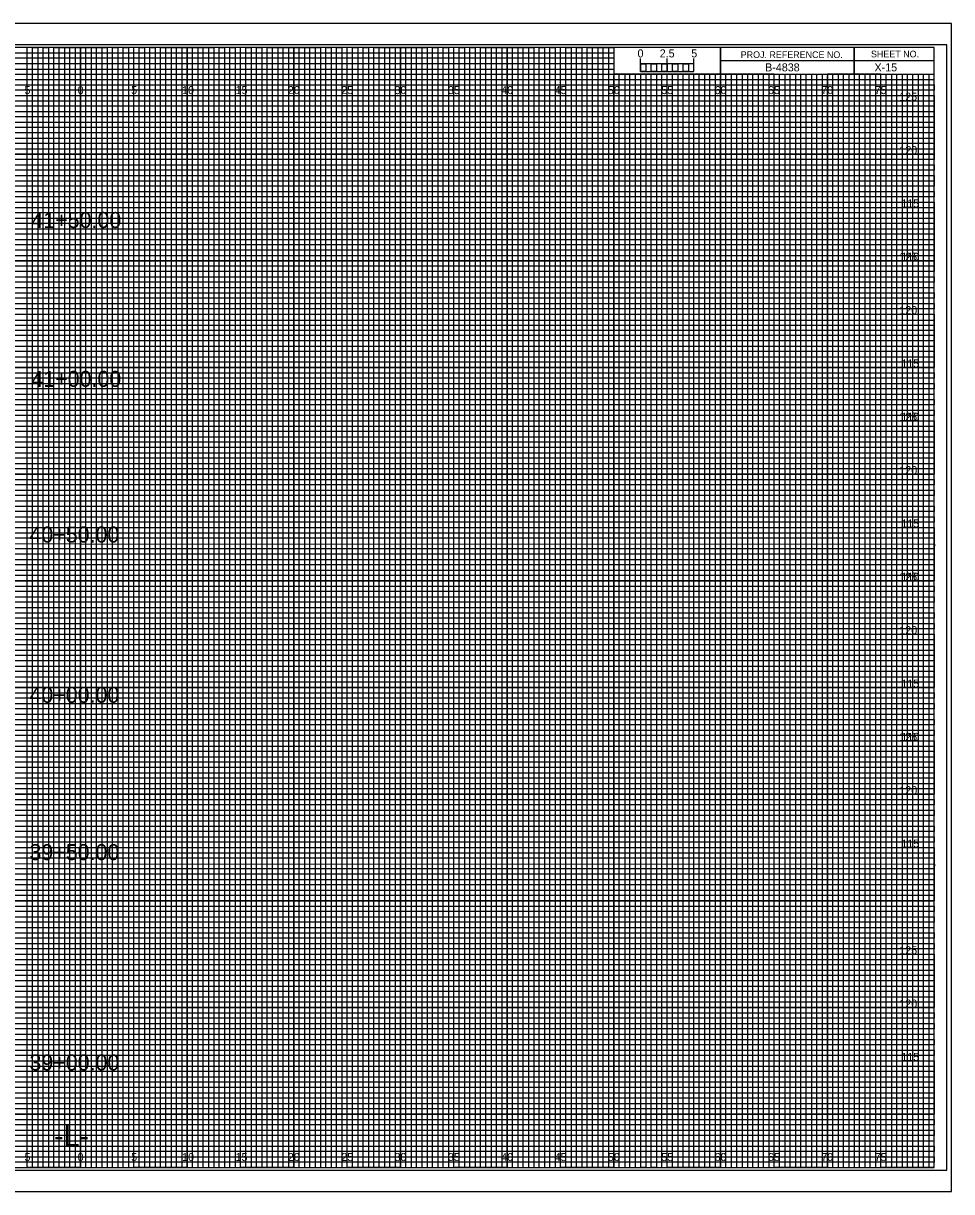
# Model space of a CAD drawing. Extents: x -7 to 182, y -2 to 1647.
# Drawn here: x 74.6 to 161.7, y 1427.8 to 1537.2 of the extents above; entities that cross this region are included whole.
import ezdxf

# ---------------------------------------------------------------- set-up
doc = ezdxf.new("R2010")
doc.units = 0
for name, color, linetype in [('Exist CMT Pavement', 7, 'Continuous'), ('Exist Cross Section Cell', 7, 'Continuous'), ('Exist XS Ground Line', 7, 'Continuous'), ('Prop CMT Pvmt Course 1', 7, 'Continuous'), ('Prop CMT Pvmt Course 2', 7, 'Continuous'), ('Prop CMT Pvmt Course 2 Wedge', 7, 'Continuous'), ('Prop CMT Pvmt Course 3', 7, 'Continuous'), ('Prop CMT Pvmt Surface', 7, 'Continuous'), ('Prop CMT Pvmt Surface Shoulder', 7, 'Continuous'), ('Prop CMT Pvmt Wedge Surface 1', 7, 'Continuous'), ('Prop CMT Pvmt Wedge Surface 2', 7, 'Continuous'), ('Prop CMT Pvmt Wedge Surface 3', 7, 'Continuous'), ('Prop CMT Shld Paved Course 1', 7, 'Continuous'), ('Prop CMT Shld Paved Course 2', 7, 'Continuous'), ('Prop CMT Shld Paved Course 3', 7, 'Continuous'), ('Prop CMT Slope Grass', 7, 'Continuous'), ('Prop CMT Subgrade Earthwork', 7, 'Continuous')]:
    doc.layers.add(name, color=color, linetype=linetype)

msp = doc.modelspace()

# ---------------------------------------------------------------- linework, layer by layer
at = {"layer": 'Exist XS Ground Line'}
for p, q in [((75, 1535), (70, 1535)), ((75, 1430), (75, 1535)), ((85, 1535), (80, 1535)), ((80, 1535), (80, 1430)), ((85, 1430), (85, 1535)), ((95, 1535), (90, 1535)), ((90, 1535), (90, 1430)), ((95, 1430), (95, 1535)), ((105, 1535), (100, 1535)), ((100, 1535), (100, 1430)), ((105, 1430), (105, 1535)), ((115, 1535), (110, 1535)), ((110, 1535), (110, 1430)), ((115, 1430), (115, 1535)), ((125, 1535), (120, 1535)), ((120, 1535), (120, 1430)), ((125, 1430), (125, 1535)), ((130, 1535), (130, 1430)), ((135, 1430), (135, 1532.5)), ((145, 1532.5), (140, 1532.5)), ((140, 1532.5), (140, 1430)), ((145, 1430), (145, 1532.5)), ((155, 1532.5), (150, 1532.5)), ((150, 1532.5), (150, 1430)), ((155, 1430), (155, 1532.5)), ((80, 1430), (75, 1430)), ((90, 1430), (85, 1430)), ((100, 1430), (95, 1430)), ((110, 1430), (105, 1430)), ((120, 1430), (115, 1430)), ((130, 1430), (125, 1430)), ((140, 1430), (135, 1430)), ((150, 1430), (145, 1430)), ((160, 1430), (155, 1430)), ((160, 1430), (160, 1430))]:
    msp.add_line(p, q, dxfattribs=at)
for points in [[(0, 1530), (160, 1530), (160, 1525), (0, 1525)], [(0, 1520), (160, 1520), (160, 1515), (0, 1515)], [(0, 1510), (160, 1510), (160, 1505), (0, 1505)], [(0, 1500), (160, 1500), (160, 1495), (0, 1495)], [(0, 1490), (160, 1490), (160, 1485), (0, 1485)], [(0, 1480), (160, 1480), (160, 1475), (0, 1475)], [(0, 1470), (160, 1470), (160, 1465), (0, 1465)], [(0, 1460), (160, 1460), (160, 1455), (0, 1455)], [(0, 1450), (160, 1450), (160, 1445), (0, 1445)], [(0, 1440), (160, 1440), (160, 1435), (0, 1435)]]:
    msp.add_lwpolyline(points, dxfattribs=at)
at = {"layer": 'Prop CMT Pvmt Course 2'}
for p, q in [((132.5, 1532.75), (132.5, 1533.95)), ((132.5, 1533.45), (132.5, 1533.95)), ((135, 1532.75), (135, 1533.95)), ((137.5, 1532.75), (137.5, 1533.95)), ((137.5, 1533.45), (137.5, 1533.95))]:
    msp.add_line(p, q, dxfattribs=at)
for points in [[(137.5, 1533.45), (132.5, 1533.45), (132.5, 1532.75), (137.5, 1532.75)], [(132.5, 1533.45), (133, 1533.45), (133, 1532.75), (132.5, 1532.75)], [(133.5, 1533.45), (134, 1533.45), (134, 1532.75), (133.5, 1532.75)], [(134.5, 1533.45), (135, 1533.45), (135, 1532.75), (134.5, 1532.75)], [(135.5, 1533.45), (136, 1533.45), (136, 1532.75), (135.5, 1532.75)], [(136.5, 1533.45), (137, 1533.45), (137, 1532.75), (136.5, 1532.75)]]:
    msp.add_lwpolyline(points, close=True, dxfattribs=at)
at = {"layer": 'Prop CMT Pvmt Course 3'}
msp.add_lwpolyline([(-6.7, 1427.75), (161.65, 1427.75), (161.65, 1537.25), (-6.7, 1537.25)], close=True, dxfattribs=at)
at = {"layer": 'Prop CMT Pvmt Wedge Surface 1'}
for p, q in [((0, 1534.5), (130, 1534.5)), ((130, 1534.5), (130, 1533.99)), ((130, 1533.99), (0, 1533.99)), ((0, 1533.5), (130, 1533.5)), ((130, 1533.5), (130, 1532.94)), ((130, 1532.94), (0, 1532.94)), ((0, 1532), (160, 1532))]:
    msp.add_line(p, q, dxfattribs=at)
for points in [[(0, 1531.5), (135, 1531.5), (160, 1531.5), (160, 1531), (0, 1531)], [(0, 1530.5), (160, 1530.5), (160, 1529.5), (0, 1529.5)], [(0, 1529), (160, 1529), (160, 1528.5), (0, 1528.49)], [(0, 1528), (160, 1528), (160, 1527), (0, 1527)], [(0, 1526.5), (160, 1526.5), (160, 1526), (0, 1526)], [(0, 1525.5), (160, 1525.5), (160, 1524.5), (0, 1524.5)], [(0, 1524), (160, 1524), (160, 1523.5), (0, 1523.5)], [(0, 1523), (160, 1523), (160, 1522), (0, 1522)], [(0, 1521.5), (160, 1521.5), (160, 1521), (0, 1521)], [(0, 1520.5), (160, 1520.5), (160, 1519.5), (0, 1519.5)], [(0, 1519), (160, 1519), (160, 1518.5), (0, 1518.5)], [(0, 1518), (160, 1518), (160, 1516.98), (160, 1516.5), (160, 1516), (0, 1516)], [(0, 1517), (160, 1517), (160, 1516.5), (0, 1516.5)], [(0, 1515.5), (160, 1515.5), (160, 1514.5), (0, 1514.52)], [(0, 1514.52), (160, 1514.5), (160, 1514), (0, 1514)], [(0, 1513.5), (160, 1513.5), (160, 1513), (0, 1513)], [(0, 1512), (160, 1512), (160, 1511.5), (0, 1511.5)], [(0, 1511), (160, 1511), (160, 1510.5), (0, 1510.5)], [(-0.04, 1509.44), (160, 1509.44), (160, 1508.94), (-0.04, 1508.94)], [(0, 1508.5), (160, 1508.5), (160, 1508), (0, 1508)], [(0, 1507), (160, 1507), (160, 1506.5), (0, 1506.5)], [(0, 1506), (160, 1506), (160, 1505.5), (0, 1505.5)], [(0, 1504.5), (160, 1504.5), (160, 1504), (0, 1504)], [(0, 1503.5), (160, 1503.5), (160, 1503), (0, 1503)], [(0, 1502), (160, 1502), (160, 1501.5), (0, 1501.5)], [(0, 1501), (160, 1501), (160, 1500.5), (0, 1500.5)], [(0, 1499.5), (160, 1499.5), (160, 1498.99), (0, 1499)], [(0, 1498.5), (160, 1498.5), (160, 1498), (0, 1498)], [(0, 1497), (160, 1497), (160, 1496.5), (0, 1496.5)], [(0, 1496), (160, 1496), (160, 1495.5), (0, 1495.5)], [(0, 1494.5), (160, 1494.5), (160, 1494), (0, 1494)], [(0, 1493.5), (160, 1493.5), (160, 1493), (0, 1493)], [(0, 1492), (160, 1492), (160, 1491.5), (0, 1491.5)], [(0, 1491), (160, 1491), (160, 1490.5), (0, 1490.5)], [(0, 1489.5), (160, 1489.5), (160, 1489), (0, 1489)], [(0, 1488.5), (160.03, 1488.45), (160, 1488), (0, 1488)], [(0, 1487), (160, 1487), (160, 1486.5), (0, 1486.5)], [(0, 1486), (160, 1486), (160, 1485.5), (0, 1485.5)], [(0, 1484.5), (160, 1484.5), (160, 1484), (0, 1484)], [(0, 1483.5), (160, 1483.5), (160, 1483), (0, 1483)], [(0, 1482), (160, 1482), (160, 1481.5), (0, 1481.5)], [(0, 1481), (160, 1481), (160, 1480.5), (0, 1480.5)], [(0, 1479.5), (160, 1479.5), (160, 1479), (0, 1479)], [(0, 1478.5), (160, 1478.5), (160, 1478), (0, 1478)], [(0, 1477), (160, 1477), (160, 1476.5), (0, 1476.5)], [(0, 1476), (160, 1476), (160, 1475.5), (0, 1475.5)], [(0, 1474.5), (160, 1474.5), (160, 1474), (0, 1474)], [(0, 1473.5), (160, 1473.5), (160, 1473), (0, 1473)], [(0, 1472), (160, 1472), (160, 1471.5), (0, 1471.5)], [(0, 1471), (160, 1471), (160, 1470.5), (0, 1470.5)], [(0, 1469.5), (160, 1469.5), (160, 1468.99), (0, 1469)], [(0, 1468.5), (160, 1468.5), (160, 1468), (0, 1468)], [(0, 1467), (160, 1467), (160, 1466.5), (0, 1466.5)], [(0, 1466), (160, 1466), (160, 1465.5), (0, 1465.5)], [(0, 1464.5), (160, 1464.5), (160, 1464), (0, 1464)], [(0, 1463.5), (160, 1463.5), (160, 1463), (0, 1463)], [(0, 1462), (160, 1462), (160, 1461.5), (0, 1461.5)], [(0, 1461), (160, 1461), (160, 1460.5), (0, 1460.5)], [(0, 1459.5), (160, 1459.5), (160, 1459), (0, 1459)], [(0, 1458.5), (160.03, 1458.45), (160, 1458), (0, 1458)], [(0, 1457), (160, 1457), (160, 1456.5), (0, 1456.5)], [(0, 1456), (160, 1456), (160, 1455.5), (0, 1455.5)], [(0, 1454.5), (160, 1454.5), (160, 1454), (0, 1454)], [(0, 1453.5), (160, 1453.5), (160, 1453), (0, 1453)], [(0, 1452), (160, 1452), (160, 1451.5), (0, 1451.5)], [(0, 1451), (160, 1451), (160, 1450.5), (0, 1450.5)], [(0, 1449.5), (160, 1449.5), (160, 1449), (0, 1449)], [(0, 1448.5), (160, 1448.5), (160, 1448), (0, 1448)], [(0, 1447), (160, 1447), (160, 1446.5), (0, 1446.5)], [(0, 1446), (160, 1446), (160, 1445.5), (0, 1445.5)], [(0, 1444.5), (160, 1444.5), (160, 1444), (0, 1444)], [(0, 1443.5), (160, 1443.5), (160, 1443), (0, 1443)], [(0, 1442), (160, 1442), (160, 1441.5), (0, 1441.5)], [(0, 1441), (160, 1441), (160, 1440.5), (0, 1440.5)], [(0, 1439.5), (160, 1439.5), (160, 1439), (0, 1439)], [(0, 1438.5), (160, 1438.5), (160, 1438), (0, 1438)], [(0, 1437), (160, 1437), (160, 1436.5), (0, 1436.5)], [(0, 1436), (160, 1436), (160, 1435.5), (0, 1435.5)], [(0, 1434.5), (160, 1434.5), (160, 1434), (0, 1434)], [(0, 1433.5), (160, 1433.5), (160, 1433), (0, 1433)], [(0, 1432), (160, 1432), (160, 1431.5), (0, 1431.5)], [(0, 1431), (160, 1431), (160, 1430.5), (0, 1430.5)]]:
    msp.add_lwpolyline(points, dxfattribs=at)
at = {"layer": 'Prop CMT Pvmt Wedge Surface 2'}
for p, q in [((152.5, 1535), (152.5, 1532.5)), ((152.5, 1532.5), (152.5, 1535)), ((160, 1533.75), (140, 1533.75)), ((140, 1533.75), (140, 1532.5)), ((140, 1532.5), (160, 1532.5))]:
    msp.add_line(p, q, dxfattribs=at)
for points in [[(160, 1535), (0, 1535), (0, 1430), (160, 1430)], [(140, 1535), (130, 1535), (130, 1532.52), (140, 1532.52)], [(160, 1535), (140, 1535), (140, 1532.5), (160, 1532.5)]]:
    msp.add_lwpolyline(points, close=True, dxfattribs=at)
at = {"layer": 'Prop CMT Pvmt Wedge Surface 3'}
for p, q in [((133.5, 1532.5), (133, 1532.5)), ((133, 1532.5), (133, 1430)), ((133.5, 1430), (133.5, 1532.5)), ((134.5, 1532.5), (134, 1532.5)), ((134, 1532.5), (134, 1430)), ((134.5, 1430), (134.5, 1532.5)), ((133, 1430), (132.5, 1430)), ((134, 1430), (133.5, 1430))]:
    msp.add_line(p, q, dxfattribs=at)
for points in [[(75, 1430), (75.5, 1430), (75.5, 1535), (76, 1535), (76, 1430)], [(76, 1430), (76.5, 1430), (76.5, 1535), (77, 1535), (77, 1430)], [(77.5, 1430), (78, 1430), (78, 1535), (78.5, 1535), (78.5, 1430)], [(78.5, 1430), (79, 1430), (79, 1535), (79.5, 1535), (79.5, 1430)], [(80, 1430), (80.5, 1430), (80.5, 1535), (81, 1535), (81, 1430)], [(81, 1430), (81.5, 1430), (81.5, 1535), (82, 1535), (82, 1430)], [(82.5, 1430), (83, 1430), (83, 1535), (83.5, 1535), (83.5, 1430)], [(83.5, 1430), (84, 1430), (84, 1535), (84.5, 1535), (84.5, 1430)], [(85, 1430), (85.5, 1430), (85.5, 1535), (86, 1535), (86, 1430)], [(86, 1430), (86.5, 1430), (86.5, 1535), (87, 1535), (87, 1430)], [(87.5, 1430), (88, 1430), (88, 1535), (88.5, 1535), (88.5, 1430)], [(88.5, 1430), (89, 1430), (89, 1535), (89.5, 1535), (89.5, 1430)], [(90, 1430), (90.5, 1430), (90.5, 1535), (91, 1535), (91, 1430)], [(91, 1430), (91.5, 1430), (91.5, 1535), (92, 1535), (92, 1430)], [(92.5, 1430), (93, 1430), (93, 1535), (93.5, 1535), (93.5, 1430)], [(93.5, 1430), (94, 1430), (94, 1535), (94.5, 1535), (94.5, 1430)], [(95, 1430), (95.5, 1430), (95.5, 1535), (96, 1535), (96, 1430)], [(96, 1430), (96.5, 1430), (96.5, 1535), (97, 1535), (97, 1430)], [(97.5, 1430), (98, 1430), (98, 1535), (98.5, 1535), (98.5, 1430)], [(98.5, 1430), (99, 1430), (99, 1535), (99.5, 1535), (99.5, 1430)], [(100, 1430), (100.5, 1430), (100.5, 1535), (101, 1535), (101, 1430)], [(101, 1430), (101.5, 1430), (101.5, 1535), (102, 1535), (102, 1430)], [(102.5, 1430), (103, 1430), (103, 1535), (103.5, 1535), (103.5, 1430)], [(103.5, 1430), (104, 1430), (104, 1535), (104.5, 1535), (104.5, 1430)], [(105, 1430), (105.5, 1430), (105.5, 1535), (106, 1535), (106, 1430)], [(106, 1430), (106.5, 1430), (106.5, 1535), (107, 1535), (107, 1430)], [(107.5, 1430), (108, 1430), (108, 1535), (108.5, 1535), (108.5, 1430)], [(108.5, 1430), (109, 1430), (109, 1535), (109.5, 1535), (109.5, 1430)], [(110, 1430), (110.5, 1430), (110.5, 1535), (111, 1535), (111, 1430)], [(111, 1430), (111.5, 1430), (111.5, 1535), (112, 1535), (112, 1430)], [(112.5, 1430), (113, 1430), (113, 1535), (113.5, 1535), (113.5, 1430)], [(113.5, 1430), (114, 1430), (114, 1535), (114.5, 1535), (114.5, 1430)], [(115, 1430), (115.5, 1430), (115.5, 1535), (116, 1535), (116, 1430)], [(116, 1430), (116.5, 1430), (116.5, 1535), (117, 1535), (117, 1430)], [(117.5, 1430), (118, 1430), (118, 1535), (118.5, 1535), (118.5, 1430)], [(118.5, 1430), (119, 1430), (119, 1535), (119.5, 1535), (119.5, 1430)], [(120, 1430), (120.5, 1430), (120.5, 1535), (121, 1535), (121, 1430)], [(121, 1430), (121.5, 1430), (121.5, 1535), (122, 1535), (122, 1430)], [(122.5, 1430), (123, 1430), (123, 1535), (123.5, 1535), (123.5, 1430)], [(123.5, 1430), (124, 1430), (124, 1535), (124.5, 1535), (124.5, 1430)], [(125, 1430), (125.5, 1430), (125.5, 1535), (126, 1535), (126, 1430)], [(126, 1430), (126.5, 1430), (126.5, 1535), (127, 1535), (127, 1430)], [(127.5, 1430), (128, 1430), (128, 1535), (128.5, 1535), (128.5, 1430)], [(128.5, 1430), (129, 1430), (129, 1535), (129.5, 1535), (129.5, 1430)], [(130, 1430), (130.5, 1430), (130.5, 1532.5), (131.01, 1532.5), (131.01, 1430)], [(131, 1430), (131.5, 1430), (131.5, 1532.5), (132, 1532.5), (132, 1430)], [(135, 1430), (135.49, 1430), (135.49, 1532.5), (136, 1532.5), (136, 1430)], [(136, 1430), (136.5, 1430), (136.5, 1532.5), (137.03, 1532.5), (137.03, 1430)], [(137.5, 1430), (138, 1430), (138, 1532.5), (138.5, 1532.5), (138.5, 1430)], [(138.5, 1430), (139, 1430), (139, 1532.5), (139.5, 1532.5), (139.5, 1430)], [(140, 1430), (140.5, 1430), (140.5, 1532.5), (141, 1532.5), (141, 1430)], [(141, 1430), (141.5, 1430), (141.5, 1532.5), (142, 1532.5), (142, 1430)], [(142.5, 1430), (143, 1430), (143, 1532.5), (143.5, 1532.5), (143.5, 1430)], [(143.5, 1430), (144, 1430), (144, 1532.5), (144.5, 1532.5), (144.5, 1430)], [(145, 1430), (145.5, 1430), (145.5, 1532.5), (146, 1532.5), (146, 1430)], [(146, 1430), (146.5, 1430), (146.5, 1532.5), (147, 1532.5), (147, 1430)], [(147.5, 1430), (148, 1430), (148, 1532.5), (148.5, 1532.5), (148.5, 1430)], [(148.5, 1430), (149, 1430), (149, 1532.5), (149.5, 1532.5), (149.5, 1430)], [(150, 1430), (150.5, 1430), (150.5, 1532.5), (151, 1532.5), (151, 1430)], [(151, 1430), (151.5, 1430), (151.5, 1532.5), (152, 1532.5), (152, 1430)], [(152.5, 1430), (153, 1430), (153, 1532.5), (153.5, 1532.5), (153.5, 1430)], [(153.5, 1430), (154, 1430), (154, 1532.5), (154.5, 1532.5), (154.5, 1430)], [(155, 1430), (155.5, 1430), (155.5, 1532.5), (156, 1532.5), (156, 1430)], [(156, 1430), (156.5, 1430), (156.5, 1532.5), (157, 1532.5), (157, 1430)], [(157.5, 1430), (158, 1430), (158, 1532.5), (158.5, 1532.5), (158.5, 1430)], [(158.5, 1430), (159, 1430), (159, 1532.5), (159.5, 1532.5), (159.5, 1430)]]:
    msp.add_lwpolyline(points, dxfattribs=at)
at = {"layer": 'Prop CMT Shld Paved Course 1'}
for p, q in [((75, 1430), (75, 1535)), ((80, 1430), (80, 1535)), ((85, 1430), (85, 1535)), ((90, 1430), (90, 1535)), ((95, 1430), (95, 1535)), ((100, 1430), (100, 1535)), ((105, 1430), (105, 1535)), ((110, 1430), (110, 1535)), ((115, 1430), (115, 1535)), ((120, 1430), (120, 1535)), ((125, 1430), (125, 1535)), ((130, 1430), (130, 1532.34)), ((135, 1430), (135, 1532.34)), ((140, 1430), (140, 1532.34)), ((145, 1430), (145, 1532.34)), ((150, 1430), (150, 1532.34)), ((155, 1430), (155, 1532.34)), ((0, 1530), (160, 1530)), ((0, 1525), (160, 1525)), ((0, 1520), (160, 1520)), ((0, 1515), (160, 1515)), ((0, 1510), (160, 1510)), ((0, 1505), (160, 1505)), ((0, 1500), (160, 1500)), ((0, 1495), (160, 1495)), ((0, 1490), (160, 1490)), ((0, 1485), (160, 1485)), ((0, 1480), (160, 1480)), ((0, 1475), (160, 1475)), ((0, 1470), (160, 1470)), ((0, 1465), (160, 1465)), ((0, 1460), (160, 1460)), ((0, 1455), (160, 1455)), ((0, 1450), (160, 1450)), ((0, 1445), (160, 1445)), ((0, 1440), (160, 1440)), ((0, 1435), (160, 1435))]:
    msp.add_line(p, q, dxfattribs=at)
at = {"layer": 'Prop CMT Shld Paved Course 2'}
for p, q in [((161.65, 1537.25), (-6.7, 1537.25)), ((-6.7, 1427.75), (161.65, 1427.75))]:
    msp.add_line(p, q, dxfattribs=at)
at = {"layer": 'Prop CMT Slope Grass'}
msp.add_lwpolyline([(-5.4, 1429.75), (161.2, 1429.75), (161.2, 1535.25), (-5.4, 1535.25)], close=True, dxfattribs=at)
at = {"layer": 'Prop CMT Subgrade Earthwork'}
for points in [[(72.5, 1430), (77.5, 1430), (77.5, 1535), (82.5, 1535), (82.5, 1430), (87.5, 1430), (87.5, 1535), (92.5, 1535), (92.5, 1430), (97.5, 1430), (97.5, 1535), (102.5, 1535), (102.5, 1430), (107.5, 1430), (107.5, 1535), (112.5, 1535), (112.5, 1430), (117.5, 1430), (117.5, 1535), (122.5, 1535), (122.5, 1430), (127.5, 1430), (127.5, 1535), (129.97, 1535), (130, 1535), (130, 1532.5), (132.5, 1532.5), (132.5, 1430), (137.5, 1430), (137.5, 1532.5), (142.5, 1532.5), (142.5, 1430), (147.5, 1430), (147.5, 1532.5), (152.5, 1532.5), (152.5, 1430), (157.5, 1430), (157.5, 1532.5)], [(0, 1532.5), (137.5, 1532.5)], [(0, 1522.5), (160, 1522.5), (160, 1527.5), (0, 1527.5)], [(0, 1512.5), (160, 1512.5), (160, 1517.5), (0, 1517.5)], [(0, 1502.5), (160, 1502.5), (160, 1507.5), (0, 1507.5)], [(0, 1492.5), (160, 1492.5), (160, 1497.5), (0, 1497.5)], [(0, 1482.5), (160, 1482.5), (160, 1487.5), (0, 1487.5)], [(0, 1472.5), (160, 1472.5), (160, 1477.5), (0, 1477.5)], [(0, 1462.5), (160, 1462.5), (160, 1467.5), (0, 1467.5)], [(0, 1452.5), (160, 1452.5), (160, 1457.5), (0, 1457.5)], [(0, 1442.5), (160, 1442.5), (160, 1447.5), (0, 1447.5)], [(0, 1432.5), (160, 1432.5), (160, 1437.5), (0, 1437.5)]]:
    msp.add_lwpolyline(points, dxfattribs=at)

# ---------------------------------------------------------------- texts
at = {"layer": 'Exist CMT Pavement'}
for s, p in [('41+50.00', (75.39, 1518.07)), ('41+00.00', (75.39, 1503.18)), ('40+50.00', (75.21, 1488.59)), ('40+00.00', (75.21, 1473.57)), ('39+50.00', (75.21, 1458.82)), ('39+00.00', (75.21, 1439.11))]:
    msp.add_text(s, height=1.5, dxfattribs=at).set_placement(p)
at = {"layer": 'Exist Cross Section Cell'}
for s, p in [('5', (74.74, 1530.62)), ('0', (79.73, 1530.62)), ('0', (79.73, 1530.62)), ('5', (84.74, 1530.62)), ('10', (89.52, 1530.62)), ('15', (94.53, 1530.62)), ('20', (99.43, 1530.62)), ('25', (104.44, 1530.62)), ('30', (109.43, 1530.62)), ('35', (114.44, 1530.62)), ('40', (119.43, 1530.62)), ('45', (124.44, 1530.62)), ('50', (129.43, 1530.62)), ('55', (134.44, 1530.62)), ('60', (139.43, 1530.62)), ('65', (144.44, 1530.62)), ('70', (149.43, 1530.62)), ('75', (154.44, 1530.62)), ('5', (74.74, 1430.62)), ('0', (79.73, 1430.62)), ('0', (79.73, 1430.62)), ('5', (84.74, 1430.62)), ('10', (89.52, 1430.62)), ('15', (94.53, 1430.62)), ('20', (99.43, 1430.62)), ('25', (104.44, 1430.62)), ('30', (109.43, 1430.62)), ('35', (114.44, 1430.62)), ('40', (119.43, 1430.62)), ('45', (124.44, 1430.62)), ('50', (129.43, 1430.62)), ('55', (134.44, 1430.62)), ('60', (139.43, 1430.62)), ('65', (144.44, 1430.62)), ('70', (149.43, 1430.62)), ('75', (154.44, 1430.62))]:
    msp.add_text(s, height=0.75, dxfattribs=at).set_placement(p)
at = {"layer": 'Prop CMT Pvmt Course 1'}
msp.add_text('-L-', height=2, dxfattribs=at).set_placement((77.53, 1432))
at = {"layer": 'Prop CMT Pvmt Course 2'}
msp.add_text('0', height=0.75, dxfattribs=at).set_placement((132.21, 1534.06))
at = {"layer": 'Prop CMT Pvmt Course 2 Wedge'}
for s, p in [('2.5', (134.29, 1534.06)), ('5', (137.24, 1534.06))]:
    msp.add_text(s, height=0.75, dxfattribs=at).set_placement(p)
at = {"layer": 'Prop CMT Pvmt Surface'}
msp.add_text('X-15', height=0.75, dxfattribs=at).set_placement((154.42, 1532.75))
at = {"layer": 'Prop CMT Pvmt Surface Shoulder'}
msp.add_text('B-4838', height=0.75, dxfattribs=at).set_placement((144.17, 1532.75))
at = {"layer": 'Prop CMT Pvmt Wedge Surface 2'}
for s, p in [('PROJ. REFERENCE NO.', (141.88, 1534)), ('SHEET NO.', (154.09, 1534.06))]:
    msp.add_text(s, height=0.625, dxfattribs=at).set_placement(p)
at = {"layer": 'Prop CMT Shld Paved Course 3'}
for s, p in [('125', (156.74, 1530)), ('120', (156.75, 1525)), ('115', (156.93, 1520)), ('125', (156.74, 1515)), ('110', (156.94, 1515)), ('120', (156.75, 1510)), ('115', (156.93, 1505)), ('125', (156.74, 1500)), ('110', (156.94, 1500)), ('120', (156.75, 1495)), ('115', (156.93, 1490)), ('125', (156.74, 1485)), ('110', (156.94, 1485)), ('120', (156.75, 1480)), ('115', (156.93, 1475)), ('125', (156.74, 1470)), ('110', (156.94, 1470)), ('120', (156.75, 1465)), ('115', (156.93, 1460)), ('125', (156.74, 1450)), ('120', (156.75, 1445)), ('115', (156.93, 1440))]:
    msp.add_text(s, height=0.75, dxfattribs=at).set_placement(p)

doc.saveas('drawing.dxf')
